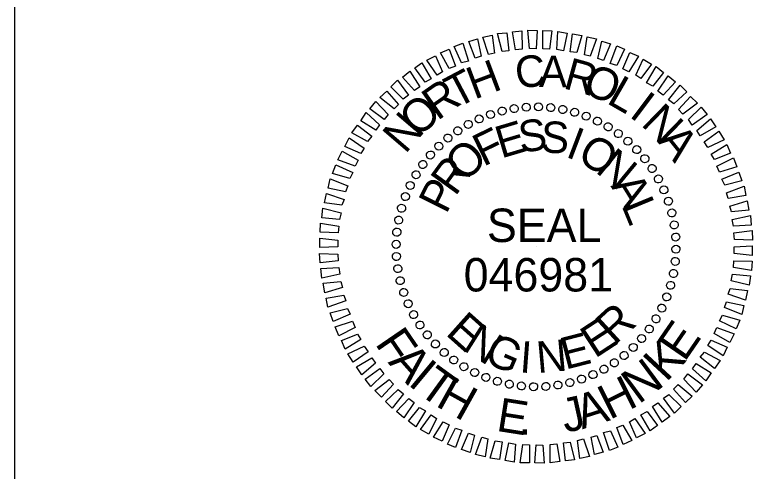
# Model space of a CAD drawing. Extents: x 2046816 to 2049224, y 578750 to 586986.
# Drawn here: x 2049015.4 to 2049148.7, y 586787.6 to 586869.4 of the extents above; entities that cross this region are included whole.
import ezdxf

# ---------------------------------------------------------------- set-up
doc = ezdxf.new("R2010")
doc.units = 0
doc.layers.add('Old_Level_2', color=7, linetype='Continuous')
doc.layers.add('Sheet PE Seal Cell', color=7, linetype='Continuous')

msp = doc.modelspace()

# ---------------------------------------------------------------- linework, layer by layer
at = {"layer": 'Old_Level_2'}
msp.add_lwpolyline([(2049015.39, 586886.21), (2049202.33, 586886.21), (2049202.33, 586774.83), (2049015.39, 586774.83)], close=True, dxfattribs=at)
at = {"layer": 'Sheet PE Seal Cell'}
for p, q in [((2049104.88, 586852.59), (2049104.88, 586852.59)), ((2049107.03, 586852.89), (2049107.03, 586852.89)), ((2049109.23, 586852.94), (2049109.23, 586852.94)), ((2049111.43, 586852.79), (2049111.43, 586852.79)), ((2049113.58, 586852.44), (2049113.58, 586852.44)), ((2049100.58, 586851.59), (2049100.58, 586851.59)), ((2049102.68, 586852.19), (2049102.68, 586852.19)), ((2049115.68, 586851.99), (2049115.68, 586851.99)), ((2049117.78, 586851.29), (2049117.78, 586851.29)), ((2049096.63, 586849.79), (2049096.63, 586849.79)), ((2049098.58, 586850.79), (2049098.58, 586850.79)), ((2049119.78, 586850.39), (2049119.78, 586850.39)), ((2049094.73, 586848.64), (2049094.73, 586848.64)), ((2049121.73, 586849.39), (2049121.73, 586849.39)), ((2049092.98, 586847.39), (2049092.98, 586847.39)), ((2049123.53, 586848.14), (2049123.53, 586848.14)), ((2049091.33, 586845.89), (2049091.33, 586845.89)), ((2049125.28, 586846.79), (2049125.28, 586846.79)), ((2049089.83, 586844.34), (2049089.83, 586844.34)), ((2049126.83, 586845.29), (2049126.83, 586845.29)), ((2049128.33, 586843.64), (2049128.33, 586843.64)), ((2049088.48, 586842.59), (2049088.48, 586842.59)), ((2049129.58, 586841.89), (2049129.58, 586841.89)), ((2049087.23, 586840.79), (2049087.23, 586840.79)), ((2049130.73, 586839.99), (2049130.73, 586839.99)), ((2049086.23, 586838.84), (2049086.23, 586838.84)), ((2049131.73, 586838.04), (2049131.73, 586838.04)), ((2049085.33, 586836.84), (2049085.33, 586836.84)), ((2049132.53, 586836.04), (2049132.53, 586836.04)), ((2049084.63, 586834.74), (2049084.63, 586834.74)), ((2049133.13, 586833.94), (2049133.13, 586833.94)), ((2049084.18, 586832.64), (2049084.18, 586832.64)), ((2049133.53, 586831.74), (2049133.53, 586831.74)), ((2049083.83, 586830.49), (2049083.83, 586830.49)), ((2049133.83, 586829.59), (2049133.83, 586829.59)), ((2049083.68, 586828.29), (2049083.68, 586828.29)), ((2049108.78, 586827.84), (2049108.78, 586827.84)), ((2049133.88, 586827.39), (2049133.88, 586827.39)), ((2049083.73, 586826.09), (2049083.73, 586826.09)), ((2049133.73, 586825.19), (2049133.73, 586825.19)), ((2049084.03, 586823.94), (2049084.03, 586823.94)), ((2049133.38, 586823.04), (2049133.38, 586823.04)), ((2049084.43, 586821.74), (2049084.43, 586821.74)), ((2049132.93, 586820.94), (2049132.93, 586820.94)), ((2049085.03, 586819.64), (2049085.03, 586819.64)), ((2049085.83, 586817.64), (2049085.83, 586817.64)), ((2049132.23, 586818.84), (2049132.23, 586818.84)), ((2049131.33, 586816.84), (2049131.33, 586816.84)), ((2049086.83, 586815.69), (2049086.83, 586815.69)), ((2049087.98, 586813.79), (2049087.98, 586813.79)), ((2049130.33, 586814.89), (2049130.33, 586814.89)), ((2049129.08, 586813.09), (2049129.08, 586813.09)), ((2049089.23, 586812.04), (2049089.23, 586812.04)), ((2049127.73, 586811.34), (2049127.73, 586811.34)), ((2049090.73, 586810.39), (2049090.73, 586810.39)), ((2049126.23, 586809.79), (2049126.23, 586809.79)), ((2049092.28, 586808.89), (2049092.28, 586808.89)), ((2049094.03, 586807.54), (2049094.03, 586807.54)), ((2049122.83, 586807.04), (2049122.83, 586807.04)), ((2049124.58, 586808.29), (2049124.58, 586808.29)), ((2049095.83, 586806.29), (2049095.83, 586806.29)), ((2049120.93, 586805.89), (2049120.93, 586805.89)), ((2049097.78, 586805.29), (2049097.78, 586805.29)), ((2049099.78, 586804.39), (2049099.78, 586804.39)), ((2049118.98, 586804.89), (2049118.98, 586804.89)), ((2049101.88, 586803.69), (2049101.88, 586803.69)), ((2049103.98, 586803.24), (2049103.98, 586803.24)), ((2049112.68, 586803.09), (2049112.68, 586803.09)), ((2049114.88, 586803.49), (2049114.88, 586803.49)), ((2049116.98, 586804.09), (2049116.98, 586804.09)), ((2049106.13, 586802.89), (2049106.13, 586802.89)), ((2049108.33, 586802.74), (2049108.33, 586802.74)), ((2049110.53, 586802.79), (2049110.53, 586802.79))]:
    msp.add_line(p, q, dxfattribs=at)
for points in [[(2049100.28, 586862.29), (2049099.23, 586865.44), (2049100.93, 586865.79), (2049101.33, 586862.54)], [(2049102.68, 586862.84), (2049101.88, 586866.04), (2049103.53, 586866.19), (2049103.88, 586862.99)], [(2049105.08, 586863.14), (2049104.53, 586866.34), (2049106.23, 586866.54), (2049106.28, 586863.29)], [(2049107.58, 586863.39), (2049107.33, 586866.64), (2049108.98, 586866.59), (2049108.78, 586863.34)], [(2049109.98, 586863.34), (2049109.98, 586866.59), (2049111.63, 586866.54), (2049111.18, 586863.29)], [(2049112.48, 586863.19), (2049112.68, 586866.44), (2049114.33, 586866.14), (2049113.68, 586862.99)], [(2049114.88, 586862.79), (2049115.33, 586865.99), (2049116.98, 586865.74), (2049116.08, 586862.64)], [(2049095.43, 586860.84), (2049094.13, 586863.74), (2049095.63, 586864.34), (2049096.68, 586861.14)], [(2049097.88, 586861.64), (2049096.73, 586864.64), (2049098.28, 586865.09), (2049098.93, 586861.99)], [(2049117.43, 586862.24), (2049117.93, 586865.49), (2049119.63, 586865.09), (2049118.48, 586861.99)], [(2049119.83, 586861.59), (2049120.58, 586864.69), (2049122.13, 586864.19), (2049120.88, 586861.24)], [(2049093.23, 586859.79), (2049091.63, 586862.59), (2049093.18, 586863.29), (2049094.33, 586860.24)], [(2049122.08, 586860.69), (2049123.23, 586863.84), (2049124.63, 586863.24), (2049123.23, 586860.34)], [(2049091.08, 586858.59), (2049089.23, 586861.29), (2049090.78, 586862.09), (2049092.03, 586859.19)], [(2049124.33, 586859.74), (2049125.58, 586862.69), (2049127.13, 586861.99), (2049125.43, 586859.19)], [(2049088.88, 586857.34), (2049087.03, 586859.89), (2049088.33, 586860.84), (2049089.98, 586857.94)], [(2049126.63, 586858.59), (2049127.98, 586861.44), (2049129.48, 586860.59), (2049127.58, 586857.99)], [(2049086.98, 586855.84), (2049084.83, 586858.24), (2049086.18, 586859.29), (2049087.93, 586856.49)], [(2049128.58, 586857.24), (2049130.33, 586860.14), (2049131.63, 586859.09), (2049129.68, 586856.64)], [(2049084.98, 586854.29), (2049082.78, 586856.49), (2049083.98, 586857.69), (2049085.93, 586854.99)], [(2049130.63, 586855.74), (2049132.48, 586858.49), (2049133.78, 586857.39), (2049131.58, 586855.04)], [(2049132.53, 586854.19), (2049134.58, 586856.79), (2049135.78, 586855.59), (2049133.48, 586853.44)], [(2049083.33, 586852.54), (2049080.78, 586854.59), (2049082.03, 586855.74), (2049084.13, 586853.34)], [(2049081.58, 586850.64), (2049078.98, 586852.59), (2049080.08, 586853.89), (2049082.28, 586851.54)], [(2049134.33, 586852.44), (2049136.48, 586854.79), (2049137.68, 586853.59), (2049135.08, 586851.64)], [(2049136.08, 586850.64), (2049138.38, 586852.89), (2049139.43, 586851.54), (2049136.78, 586849.64)], [(2049080.08, 586848.74), (2049077.38, 586850.44), (2049078.33, 586851.89), (2049080.73, 586849.69)], [(2049137.58, 586848.69), (2049140.03, 586850.79), (2049140.98, 586849.34), (2049138.18, 586847.74)], [(2049078.58, 586846.74), (2049075.78, 586848.24), (2049076.78, 586849.64), (2049079.38, 586847.64)], [(2049138.88, 586846.64), (2049141.53, 586848.54), (2049142.48, 586847.04), (2049139.58, 586845.64)], [(2049077.38, 586844.59), (2049074.53, 586845.84), (2049075.28, 586847.39), (2049077.98, 586845.54)], [(2049140.18, 586844.44), (2049142.98, 586846.19), (2049143.63, 586844.64), (2049140.78, 586843.49)], [(2049076.38, 586842.29), (2049073.28, 586843.44), (2049074.03, 586844.99), (2049076.88, 586843.39)], [(2049141.18, 586842.29), (2049144.13, 586843.79), (2049144.78, 586842.19), (2049141.68, 586841.19)], [(2049075.38, 586840.09), (2049072.28, 586840.99), (2049072.93, 586842.54), (2049075.93, 586841.14)], [(2049142.08, 586839.94), (2049145.13, 586841.24), (2049145.68, 586839.69), (2049142.58, 586838.89)], [(2049074.63, 586837.69), (2049071.53, 586838.34), (2049071.88, 586839.99), (2049075.03, 586838.74)], [(2049142.88, 586837.54), (2049146.08, 586838.69), (2049146.38, 586837.04), (2049143.23, 586836.49)], [(2049073.98, 586835.29), (2049070.88, 586835.69), (2049071.23, 586837.39), (2049074.38, 586836.34)], [(2049143.48, 586835.14), (2049146.63, 586836.09), (2049146.93, 586834.39), (2049143.78, 586834.09)], [(2049073.58, 586832.74), (2049070.38, 586833.04), (2049070.58, 586834.74), (2049073.83, 586833.94)], [(2049143.93, 586832.74), (2049147.18, 586833.44), (2049147.33, 586831.74), (2049144.13, 586831.54)], [(2049073.33, 586830.34), (2049070.08, 586830.44), (2049070.18, 586832.09), (2049073.43, 586831.54)], [(2049144.23, 586830.34), (2049147.48, 586830.74), (2049147.58, 586829.04), (2049144.33, 586829.14)], [(2049073.28, 586827.84), (2049070.03, 586827.69), (2049070.03, 586829.39), (2049073.28, 586829.04)], [(2049144.28, 586827.84), (2049147.53, 586827.99), (2049147.53, 586826.29), (2049144.28, 586826.64)], [(2049073.33, 586825.34), (2049070.08, 586824.94), (2049069.98, 586826.64), (2049073.23, 586826.54)], [(2049144.23, 586825.34), (2049147.48, 586825.24), (2049147.38, 586823.59), (2049144.13, 586824.14)], [(2049073.63, 586822.94), (2049070.38, 586822.24), (2049070.23, 586823.94), (2049073.43, 586824.14)], [(2049143.98, 586822.94), (2049147.18, 586822.64), (2049146.98, 586820.94), (2049143.73, 586821.74)], [(2049074.08, 586820.54), (2049070.93, 586819.59), (2049070.63, 586821.29), (2049073.78, 586821.59)], [(2049143.58, 586820.39), (2049146.68, 586819.99), (2049146.33, 586818.29), (2049143.18, 586819.34)], [(2049074.68, 586818.14), (2049071.48, 586816.99), (2049071.18, 586818.64), (2049074.33, 586819.19)], [(2049142.93, 586817.99), (2049146.03, 586817.34), (2049145.68, 586815.69), (2049142.53, 586816.94)], [(2049075.48, 586815.74), (2049072.43, 586814.44), (2049071.88, 586815.99), (2049074.98, 586816.79)], [(2049142.18, 586815.59), (2049145.28, 586814.69), (2049144.63, 586813.14), (2049141.63, 586814.54)], [(2049076.38, 586813.39), (2049073.43, 586811.89), (2049072.78, 586813.49), (2049075.88, 586814.49)], [(2049141.18, 586813.39), (2049144.28, 586812.24), (2049143.53, 586810.69), (2049140.68, 586812.29)], [(2049077.38, 586811.24), (2049074.58, 586809.49), (2049073.93, 586811.04), (2049076.78, 586812.19)], [(2049140.18, 586811.09), (2049143.03, 586809.84), (2049142.28, 586808.29), (2049139.58, 586810.14)], [(2049078.68, 586809.04), (2049076.03, 586807.14), (2049075.08, 586808.64), (2049077.98, 586810.04)], [(2049138.98, 586808.94), (2049141.78, 586807.44), (2049140.78, 586806.04), (2049138.18, 586808.04)], [(2049079.98, 586806.99), (2049077.53, 586804.89), (2049076.58, 586806.34), (2049079.38, 586807.94)], [(2049081.48, 586805.04), (2049079.18, 586802.79), (2049078.13, 586804.14), (2049080.78, 586806.04)], [(2049137.48, 586806.94), (2049140.18, 586805.24), (2049139.23, 586803.79), (2049136.83, 586805.99)], [(2049135.98, 586805.04), (2049138.58, 586803.09), (2049137.48, 586801.79), (2049135.28, 586804.14)], [(2049083.23, 586803.24), (2049081.08, 586800.89), (2049079.88, 586802.09), (2049082.48, 586804.04)], [(2049134.23, 586803.14), (2049136.78, 586801.09), (2049135.53, 586799.94), (2049133.43, 586802.34)], [(2049085.03, 586801.49), (2049082.98, 586798.89), (2049081.78, 586800.09), (2049084.08, 586802.24)], [(2049086.93, 586799.94), (2049085.08, 586797.19), (2049083.78, 586798.29), (2049085.98, 586800.64)], [(2049132.58, 586801.39), (2049134.78, 586799.19), (2049133.58, 586797.99), (2049131.63, 586800.69)], [(2049088.98, 586798.44), (2049087.23, 586795.54), (2049085.93, 586796.59), (2049087.88, 586799.04)], [(2049130.58, 586799.84), (2049132.73, 586797.44), (2049131.38, 586796.39), (2049129.63, 586799.19)], [(2049090.93, 586797.09), (2049089.58, 586794.24), (2049088.08, 586795.09), (2049089.98, 586797.69)], [(2049128.68, 586798.34), (2049130.53, 586795.79), (2049129.23, 586794.84), (2049127.58, 586797.74)], [(2049093.23, 586795.94), (2049091.98, 586792.99), (2049090.43, 586793.69), (2049092.13, 586796.49)], [(2049126.48, 586797.09), (2049128.33, 586794.39), (2049126.78, 586793.59), (2049125.53, 586796.49)], [(2049095.48, 586794.99), (2049094.33, 586791.84), (2049092.93, 586792.44), (2049094.33, 586795.34)], [(2049124.33, 586795.89), (2049125.93, 586793.09), (2049124.38, 586792.39), (2049123.23, 586795.44)], [(2049097.73, 586794.09), (2049096.98, 586790.99), (2049095.43, 586791.49), (2049096.68, 586794.44)], [(2049100.13, 586793.44), (2049099.63, 586790.19), (2049097.93, 586790.59), (2049099.08, 586793.69)], [(2049119.68, 586794.04), (2049120.83, 586791.04), (2049119.28, 586790.59), (2049118.63, 586793.69)], [(2049122.13, 586794.84), (2049123.43, 586791.94), (2049121.93, 586791.34), (2049120.88, 586794.54)], [(2049102.68, 586792.89), (2049102.23, 586789.69), (2049100.58, 586789.94), (2049101.48, 586793.04)], [(2049105.08, 586792.49), (2049104.88, 586789.24), (2049103.23, 586789.54), (2049103.88, 586792.69)], [(2049107.58, 586792.34), (2049107.58, 586789.09), (2049105.93, 586789.14), (2049106.38, 586792.39)], [(2049109.98, 586792.29), (2049110.23, 586789.04), (2049108.58, 586789.09), (2049108.78, 586792.34)], [(2049112.48, 586792.54), (2049113.03, 586789.34), (2049111.33, 586789.14), (2049111.28, 586792.39)], [(2049114.88, 586792.84), (2049115.68, 586789.64), (2049114.03, 586789.49), (2049113.68, 586792.69)], [(2049117.28, 586793.39), (2049118.33, 586790.24), (2049116.63, 586789.89), (2049116.23, 586793.14)]]:
    msp.add_lwpolyline(points, close=True, dxfattribs=at)
for centre, major_axis in [((2049100.61, 586851.55), (-0.234, 0.681)), ((2049102.71, 586852.17), (-0.174, 0.699)), ((2049104.85, 586852.61), (-0.113, 0.711)), ((2049107.03, 586852.86), (-0.05, 0.718)), ((2049109.21, 586852.92), (0.013, 0.72)), ((2049111.4, 586852.78), (0.075, 0.716)), ((2049113.56, 586852.46), (0.137, 0.707)), ((2049115.69, 586851.95), (0.198, 0.692)), ((2049098.58, 586850.75), (-0.293, 0.658)), ((2049117.76, 586851.25), (0.258, 0.672)), ((2049119.77, 586850.38), (0.316, 0.647)), ((2049096.62, 586849.78), (-0.349, 0.63)), ((2049121.69, 586849.34), (0.371, 0.617)), ((2049094.75, 586848.63), (-0.403, 0.597)), ((2049123.52, 586848.13), (0.423, 0.582)), ((2049092.99, 586847.33), (-0.453, 0.56)), ((2049125.23, 586846.77), (0.472, 0.543)), ((2049091.35, 586845.88), (-0.5, 0.518)), ((2049126.82, 586845.26), (0.518, 0.5)), ((2049089.85, 586844.29), (-0.543, 0.472)), ((2049128.27, 586843.62), (0.56, 0.453)), ((2049088.49, 586842.58), (-0.582, 0.423)), ((2049129.57, 586841.86), (0.597, 0.403)), ((2049087.28, 586840.76), (-0.617, 0.371)), ((2049130.71, 586840), (0.63, 0.349)), ((2049086.23, 586838.83), (-0.647, 0.316)), ((2049085.36, 586836.83), (-0.672, 0.258)), ((2049131.69, 586838.04), (0.658, 0.293)), ((2049132.49, 586836.01), (0.681, 0.234)), ((2049084.67, 586834.75), (-0.692, 0.198)), ((2049133.11, 586833.91), (0.699, 0.174)), ((2049084.16, 586832.63), (-0.707, 0.137)), ((2049133.55, 586831.76), (0.711, 0.113)), ((2049083.83, 586830.46), (-0.716, 0.075)), ((2049133.8, 586829.59), (0.718, 0.05)), ((2049083.7, 586828.28), (-0.72, 0.013)), ((2049133.85, 586827.4), (0.72, -0.013)), ((2049083.76, 586826.09), (-0.718, -0.05)), ((2049133.72, 586825.22), (0.716, -0.075)), ((2049084.01, 586823.92), (-0.711, -0.113)), ((2049133.4, 586823.05), (0.707, -0.137)), ((2049084.44, 586821.77), (-0.699, -0.174)), ((2049132.88, 586820.93), (0.692, -0.198)), ((2049085.06, 586819.67), (-0.681, -0.234)), ((2049132.19, 586818.85), (0.672, -0.258)), ((2049085.86, 586817.64), (-0.658, -0.293)), ((2049131.32, 586816.85), (0.647, -0.316)), ((2049086.84, 586815.68), (-0.63, -0.349)), ((2049130.27, 586814.92), (0.617, -0.371)), ((2049087.98, 586813.82), (-0.597, -0.403)), ((2049129.07, 586813.1), (0.582, -0.423)), ((2049089.29, 586812.06), (-0.56, -0.453)), ((2049090.74, 586810.42), (-0.518, -0.5)), ((2049127.7, 586811.39), (0.543, -0.472)), ((2049092.32, 586808.91), (-0.472, -0.543)), ((2049126.2, 586809.8), (0.5, -0.518)), ((2049094.03, 586807.55), (-0.423, -0.582)), ((2049124.56, 586808.35), (0.453, -0.56)), ((2049095.86, 586806.34), (-0.371, -0.617)), ((2049122.8, 586807.05), (0.403, -0.597)), ((2049097.78, 586805.3), (-0.316, -0.647)), ((2049118.98, 586804.93), (0.293, -0.658)), ((2049120.94, 586805.9), (0.349, -0.63)), ((2049099.79, 586804.43), (-0.258, -0.672)), ((2049101.86, 586803.73), (-0.198, -0.692)), ((2049116.94, 586804.13), (0.234, -0.681)), ((2049103.99, 586803.22), (-0.137, -0.707)), ((2049106.15, 586802.9), (-0.075, -0.716)), ((2049108.34, 586802.76), (-0.013, -0.72)), ((2049110.53, 586802.82), (0.05, -0.718)), ((2049112.7, 586803.07), (0.113, -0.711)), ((2049114.84, 586803.5), (0.174, -0.699))]:
    msp.add_ellipse(centre, major_axis=major_axis, ratio=0.999708, dxfattribs=at)

# ---------------------------------------------------------------- texts
for s, height, rotation, p in [('C', 5.66, 6.2199, (2049105.33, 586856.19)), ('A', 5.64, 359.0203, (2049109.28, 586856.49)), ('R', 5.73, 344.6211, (2049113.48, 586856.29)), ('H', 5.79, 20.6195, (2049097.73, 586854.19)), ('T', 5.86, 27.8198, (2049094.48, 586852.54)), ('O', 5.81, 337.4212, (2049116.83, 586855.54)), ('L', 5.88, 330.2209, (2049121.23, 586853.69)), ('R', 5.91, 35.0205, (2049091.08, 586850.34)), ('I', 5.92, 323.0201, (2049125.28, 586851.29)), ('O', 5.93, 42.2217, (2049087.63, 586847.24)), ('N', 5.93, 315.8189, (2049127.43, 586849.74)), ('N', 5.91, 49.4235, (2049085.33, 586844.34)), ('E', 5.75, 16.6111, (2049102.53, 586843.64)), ('S', 5.66, 7.2556, (2049105.98, 586844.69)), ('S', 5.64, 357.9004, (2049109.58, 586844.74)), ('F', 5.84, 25.967, (2049099.33, 586842.14)), ('I', 5.79, 339.1896, (2049113.88, 586844.04)), ('A', 5.9, 308.6172, (2049130.38, 586846.79)), ('O', 5.88, 329.8335, (2049115.88, 586843.34)), ('O', 5.93, 44.6812, (2049096.03, 586839.19)), ('N', 5.93, 320.4766, (2049119.23, 586841.34)), ('R', 5.88, 54.0397, (2049094.28, 586836.74)), ('P', 5.8, 63.3989, (2049092.68, 586833.54)), ('A', 5.85, 301.7603, (2049122.08, 586838.74)), ('L', 5.76, 292.4008, (2049124.03, 586835.29)), ('SEAL', 5.998, 360, (2049099.98, 586828.69)), ('R', 5.93, 42.4814, (2049122.88, 586810.09)), ('E', 5.93, 318.2769, (2049092.38, 586812.19)), ('E', 5.9, 33.1241, (2049119.33, 586807.74)), ('N', 5.9, 327.634, (2049095.38, 586809.49)), ('E', 6.25, 55.493, (2049135.38, 586807.05)), ('F', 6.24, 304.4142, (2049079.81, 586810.5)), ('E', 5.72, 14.4118, (2049114.03, 586805.79)), ('G', 5.82, 336.9902, (2049099.18, 586807.24)), ('N', 5.65, 5.0564, (2049109.08, 586805.19)), ('K', 6.3, 47.2091, (2049132.11, 586803.43)), ('I', 5.65, 355.7012, (2049105.73, 586805.34)), ('A', 6.29, 311.4309, (2049082.14, 586807.09)), ('I', 6.3, 320.2712, (2049085.65, 586803.24)), ('N', 6.3, 36.4833, (2049127.16, 586799.52)), ('T', 6.29, 324.0731, (2049087.33, 586801.76)), ('H', 6.25, 330.8733, (2049090.57, 586799.41)), ('H', 6.22, 26.4993, (2049121.97, 586796.76)), ('A', 6.12, 17.659, (2049117.03, 586795.1)), ('E', 6.04, 351.0577, (2049101.5, 586794.87)), ('J', 6.07, 12.4012, (2049114, 586794.48)), ('.', 6, 358.167, (2049105.64, 586794.22))]:
    msp.add_text(s, height=height, rotation=rotation, dxfattribs=at).set_placement(p)
msp.add_text('046981', height=5.998, dxfattribs=at).set_placement((2049095.81, 586819.83))

doc.saveas('drawing.dxf')
